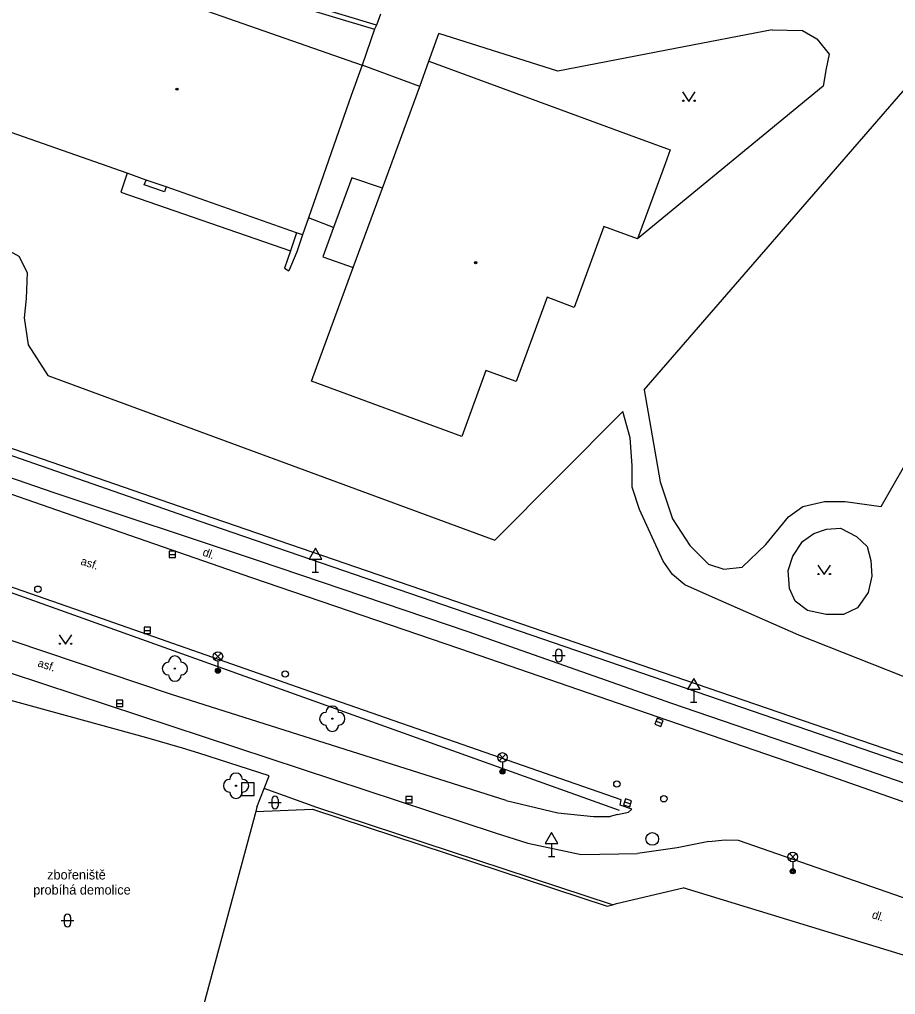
# Model space of a CAD drawing. Extents: x -598233 to -596890, y -1157848 to -1156431.
# Drawn here: x -598177.1 to -598107.9, y -1157427.1 to -1157350.2 of the extents above; entities that cross this region are included whole.
import ezdxf

# ---------------------------------------------------------------- set-up
doc = ezdxf.new("R2010")
doc.units = 0
for name, color, linetype in [('Level 10', 7, 'Continuous'), ('Level 11', 7, 'Continuous'), ('Level 22', 7, 'Continuous'), ('Level 26', 7, 'Continuous'), ('Level 27', 7, 'Continuous'), ('Level 28', 7, 'Continuous'), ('Level 33', 7, 'Continuous'), ('Level 34', 7, 'Continuous'), ('Level 36', 7, 'Continuous'), ('Level 39', 7, 'Continuous'), ('Level 40', 7, 'Continuous'), ('Level 42', 7, 'Continuous'), ('Level 5', 7, 'Continuous'), ('Level 7', 7, 'Continuous'), ('Level 9', 7, 'Continuous')]:
    doc.layers.add(name, color=color, linetype=linetype)

msp = doc.modelspace()

# ---------------------------------------------------------------- linework, layer by layer
at = {"layer": 'Level 10'}
for points in [[(-598129.85, -1157412.91), (-598128.99, -1157412.74), (-598128.74, -1157412.49), (-598129.64, -1157412.18), (-598129.56, -1157411.75), (-598154.06, -1157403.22), (-598172.16, -1157396.89), (-598187.22, -1157391.65), (-598196.64, -1157388.37), (-598205.7, -1157385.01), (-598210.18, -1157383.02), (-598212.78, -1157381.51), (-598215.97, -1157379.65), (-598220.53, -1157375.86), (-598224.65, -1157371.2), (-598227.62, -1157366.41), (-598230.19, -1157360.94), (-598232.8901, -1157353.658)], [(-598174.73, -1157388.67), (-598186.98, -1157384.41)], [(-598217.58, -1157387.43), (-598207.01, -1157391.49), (-598196.87, -1157395.42), (-598177.79, -1157401.73), (-598139.52, -1157414.37), (-598136.95, -1157415.18), (-598132.7199, -1157416.07)], [(-598158.72, -1157394.22), (-598174.73, -1157388.67)], [(-598165.15, -1157403.42), (-598194.77, -1157393.44)], [(-598142.31, -1157399.84), (-598158.72, -1157394.22)], [(-598125.89, -1157405.48), (-598142.31, -1157399.84)], [(-598138.65, -1157411.8), (-598165.15, -1157403.42)], [(-598113.03, -1157409.92), (-598125.89, -1157405.48)], [(-598099.81, -1157414.54), (-598113.03, -1157409.92)], [(-598138.65, -1157411.8), (-598134.58, -1157412.79), (-598131.75, -1157413.07), (-598130.77, -1157413.07), (-598130.43, -1157413.07)], [(-598129.85, -1157412.9099), (-598130.43, -1157413.07)], [(-598122.65, -1157415.04), (-598125.15, -1157415.53)], [(-598122.65, -1157415.04), (-598121.35, -1157414.91), (-598120.33, -1157414.94), (-598106.78, -1157419.65), (-598093.77, -1157424.14)], [(-598132.7199, -1157416.07), (-598128.27, -1157415.98)], [(-598125.15, -1157415.53), (-598128.27, -1157415.98)]]:
    msp.add_lwpolyline(points, dxfattribs=at)
at = {"layer": 'Level 11'}
for points in [[(-598173.1599, -1157343.7199), (-598172.18, -1157343.98), (-598149.05, -1157350.93)], [(-598148.88, -1157350.6), (-598173, -1157343.32)], [(-598148.56, -1157349.73), (-598148.88, -1157350.6)], [(-598148.88, -1157350.6), (-598149.05, -1157350.93)], [(-598149.05, -1157350.93), (-598150.01, -1157353.76)], [(-598144.74, -1157353.46), (-598143.95, -1157351.26)], [(-598117.66, -1157350.97), (-598125.31, -1157352.45), (-598134.56, -1157354.23), (-598143.95, -1157351.26)], [(-598117.66, -1157350.97), (-598115.26, -1157351.03), (-598114.12, -1157351.68), (-598113.15, -1157352.9), (-598113.39, -1157354.03), (-598113.63, -1157355.41), (-598128.27, -1157367.48)], [(-598127.76, -1157379.4), (-598105.11, -1157353.26), (-598103.49, -1157352.53), (-598101.95, -1157352.61), (-598100.57, -1157353.26), (-598094.72, -1157358.86), (-598072.97, -1157374.04), (-598069.72, -1157379.07), (-598068.1, -1157382.56), (-598068.18, -1157401.07)], [(-598145.47, -1157355.44), (-598150.01, -1157353.76)], [(-598168.56, -1157362.28), (-598169.07, -1157363.8), (-598155.68, -1157368.43)], [(-598165.48, -1157363.38), (-598167.07, -1157362.84)], [(-598148.42, -1157363.47), (-598150.83, -1157362.66), (-598152.27, -1157366.59), (-598154.26, -1157365.82)], [(-598152.27, -1157366.59), (-598153.11, -1157368.9), (-598150.72, -1157369.74)], [(-598154.7199, -1157367.15), (-598155.18, -1157368.49), (-598155.79, -1157370)], [(-598155.21, -1157367), (-598155.68, -1157368.43)], [(-598178.85, -1157367.89), (-598177.11, -1157368.85), (-598176.46, -1157370.14), (-598176.54, -1157372.17), (-598176.7, -1157373.72), (-598176.38, -1157375.83), (-598174.83, -1157378.26), (-598139.53, -1157391.25), (-598129.45, -1157381.1)], [(-598155.68, -1157368.43), (-598156.14, -1157369.8), (-598155.79, -1157370)], [(-598202.41, -1157378.51), (-598201.88, -1157377.34), (-598199.89, -1157378.28), (-598197.68, -1157379.21), (-598186.88, -1157383.19), (-598174.34, -1157387.5), (-598158.22, -1157392.86), (-598141.67, -1157398.47), (-598125.59, -1157404.13), (-598112.45, -1157408.63), (-598099.7, -1157413.02), (-598085.56, -1157417.95), (-598077.95, -1157420.37), (-598077.74, -1157419.93), (-598077.36, -1157419.11)], [(-598127.76, -1157379.4), (-598126.5, -1157386.66), (-598125.53, -1157389.58), (-598124.15, -1157391.69), (-598122.68, -1157393.15), (-598121.47, -1157393.56), (-598120.01, -1157393.4), (-598118.14, -1157391.61), (-598116.35, -1157389.42), (-598115.22, -1157388.61), (-598113.51, -1157388.2), (-598111.89, -1157388.2), (-598109.05, -1157388.61), (-598106.45, -1157384.06)], [(-598067.75, -1157403.84), (-598075.93, -1157407.12), (-598081.37, -1157408.25), (-598086.89, -1157408.09), (-598089.65, -1157407.68), (-598092.98, -1157407.28), (-598096.96, -1157406.3), (-598101.58, -1157404.27), (-598115.54, -1157398.76), (-598122.36, -1157395.75), (-598124.55, -1157394.78), (-598125.53, -1157393.97), (-598126.26, -1157392.91), (-598128.12, -1157388.85), (-598128.69, -1157387.07), (-598128.69, -1157385.36), (-598128.85, -1157383.17), (-598129.45, -1157381.1)], [(-598112.26, -1157390.31), (-598111, -1157390.96), (-598110.14, -1157391.77), (-598109.86, -1157392.87), (-598109.78, -1157394.09), (-598110.06, -1157395.39), (-598110.92, -1157396.6), (-598112.01, -1157397.13), (-598113.39, -1157397.13), (-598114.85, -1157396.81), (-598115.83, -1157396.08), (-598116.27, -1157395.06), (-598116.39, -1157393.64), (-598116.03, -1157392.51), (-598115.26, -1157391.37), (-598114.37, -1157390.72), (-598113.35, -1157390.4), (-598112.26, -1157390.31)], [(-598167, -1157406.85), (-598178.21, -1157403.79)], [(-598164.19, -1157407.68), (-598167, -1157406.85)], [(-598162.92, -1157408.06), (-598164.19, -1157407.68)], [(-598157.35, -1157409.87), (-598162.92, -1157408.06)], [(-598157.74, -1157410.85), (-598157.35, -1157409.87)], [(-598158.33, -1157412.34), (-598157.74, -1157410.85)], [(-598153.6, -1157412.35), (-598157.74, -1157410.85)], [(-598158.33, -1157412.34), (-598158.42, -1157412.68), (-598162.51, -1157427.88)], [(-598130.26, -1157420.05), (-598153.6, -1157412.35)]]:
    msp.add_lwpolyline(points, dxfattribs=at)
at = {"layer": 'Level 22'}
for centre in [(-598164.8, -1157401.4), (-598152.37, -1157405.35), (-598159.97, -1157410.64)]:
    msp.add_circle(centre, 0.05, dxfattribs=at)
for centre, start, end in [((-598164.8, -1157400.9), 0, 180), ((-598165.3, -1157401.4), 90, 270), ((-598164.3, -1157401.4), 270, 90), ((-598164.8, -1157401.9), 180, 0), ((-598152.37, -1157404.85), 0, 180), ((-598152.87, -1157405.35), 90, 270), ((-598151.87, -1157405.35), 270, 90), ((-598152.37, -1157405.85), 180, 0), ((-598159.97, -1157410.14), 0, 180), ((-598160.47, -1157410.64), 90, 270), ((-598159.47, -1157410.64), 270, 90), ((-598159.97, -1157411.14), 180, 0)]:
    msp.add_arc(centre, 0.5, start, end, dxfattribs=at)
at = {"layer": 'Level 26'}
msp.add_lwpolyline([(-598159.53, -1157411.41), (-598158.53, -1157411.41), (-598158.53, -1157410.41), (-598159.53, -1157410.41)], close=True, dxfattribs=at)
at = {"layer": 'Level 27'}
for p, q in [((-598165.24, -1157392.38), (-598164.74, -1157392.38)), ((-598167.23, -1157398.38), (-598166.73, -1157398.38)), ((-598169.4, -1157404.15), (-598168.9, -1157404.15)), ((-598126.8145, -1157405.5534), (-598126.3455, -1157405.7266)), ((-598146.58, -1157411.74), (-598146.08, -1157411.74)), ((-598129.2989, -1157411.9162), (-598128.8211, -1157412.0638))]:
    msp.add_line(p, q, dxfattribs=at)
for points in [[(-598165.24, -1157392.63), (-598164.74, -1157392.63), (-598164.74, -1157392.13), (-598165.24, -1157392.13)], [(-598167.23, -1157398.63), (-598166.73, -1157398.63), (-598166.73, -1157398.13), (-598167.23, -1157398.13)], [(-598169.4, -1157404.4), (-598168.9, -1157404.4), (-598168.9, -1157403.9), (-598169.4, -1157403.9)], [(-598126.9011, -1157405.7879), (-598126.4321, -1157405.9611), (-598126.2589, -1157405.4921), (-598126.7279, -1157405.3189)], [(-598146.58, -1157411.99), (-598146.08, -1157411.99), (-598146.08, -1157411.49), (-598146.58, -1157411.49)], [(-598129.3727, -1157412.1551), (-598128.8949, -1157412.3027), (-598128.7473, -1157411.8249), (-598129.2251, -1157411.6773)]]:
    msp.add_lwpolyline(points, close=True, dxfattribs=at)
msp.add_circle((-598127.11, -1157414.84), 0.5, dxfattribs=at)
at = {"layer": 'Level 28'}
for centre in [(-598175.61, -1157395.13), (-598156.09, -1157401.82), (-598129.9099, -1157410.5), (-598126.2, -1157411.67)]:
    msp.add_circle(centre, 0.25, dxfattribs=at)
at = {"layer": 'Level 33'}
for p, q in [((-598161.665, -1157400.7), (-598161.135, -1157400.17)), ((-598161.665, -1157400.17), (-598161.135, -1157400.7)), ((-598161.4, -1157400.81), (-598161.4, -1157401.56)), ((-598139.205, -1157408.67), (-598138.675, -1157408.14)), ((-598139.205, -1157408.14), (-598138.675, -1157408.67)), ((-598138.94, -1157408.78), (-598138.94, -1157409.53)), ((-598116.295, -1157416.53), (-598115.765, -1157416)), ((-598116.295, -1157416), (-598115.765, -1157416.53)), ((-598116.03, -1157416.64), (-598116.03, -1157417.39))]:
    msp.add_line(p, q, dxfattribs=at)
for centre, radius in [((-598161.4, -1157400.435), 0.375), ((-598161.4, -1157401.56), 0.2), ((-598161.4, -1157401.56), 0.1445), ((-598161.4, -1157401.56), 0.0876), ((-598138.94, -1157408.405), 0.375), ((-598138.94, -1157409.53), 0.2), ((-598138.94, -1157409.53), 0.1445), ((-598138.94, -1157409.53), 0.0876), ((-598116.03, -1157416.265), 0.375), ((-598116.03, -1157417.39), 0.2), ((-598116.03, -1157417.39), 0.1445), ((-598116.03, -1157417.39), 0.0876)]:
    msp.add_circle(centre, radius, dxfattribs=at)
at = {"layer": 'Level 34'}
for p, q in [((-598153.71, -1157392.762), (-598153.71, -1157393.78)), ((-598153.96, -1157393.78), (-598153.46, -1157393.78)), ((-598123.84, -1157403.032), (-598123.84, -1157404.05)), ((-598124.09, -1157404.05), (-598123.59, -1157404.05)), ((-598135.06, -1157415.202), (-598135.06, -1157416.22)), ((-598135.31, -1157416.22), (-598134.81, -1157416.22))]:
    msp.add_line(p, q, dxfattribs=at)
for points in [[(-598154.21, -1157392.762), (-598153.21, -1157392.762), (-598153.71, -1157391.896)], [(-598124.34, -1157403.032), (-598123.34, -1157403.032), (-598123.84, -1157402.166)], [(-598135.56, -1157415.202), (-598134.56, -1157415.202), (-598135.06, -1157414.336)]]:
    msp.add_lwpolyline(points, close=True, dxfattribs=at)
at = {"layer": 'Level 36'}
for p, q in [((-598134.996, -1157400.366), (-598133.996, -1157400.366)), ((-598134.746, -1157400.116), (-598134.746, -1157400.616)), ((-598134.246, -1157400.116), (-598134.246, -1157400.616)), ((-598157.396, -1157411.966), (-598156.396, -1157411.966)), ((-598157.146, -1157411.716), (-598157.146, -1157412.216)), ((-598156.646, -1157411.716), (-598156.646, -1157412.216)), ((-598173.776, -1157421.276), (-598172.776, -1157421.276)), ((-598173.526, -1157421.026), (-598173.526, -1157421.526)), ((-598173.026, -1157421.026), (-598173.026, -1157421.526))]:
    msp.add_line(p, q, dxfattribs=at)
for points in [[(-598124.72, -1157355.87), (-598124.22, -1157356.62), (-598123.72, -1157355.87)], [(-598114.04, -1157393.23), (-598113.54, -1157393.98), (-598113.04, -1157393.23)], [(-598173.93, -1157398.73), (-598173.43, -1157399.48), (-598172.93, -1157398.73)]]:
    msp.add_lwpolyline(points, dxfattribs=at)
for centre in [(-598124.6702, -1157356.5698), (-598123.7708, -1157356.5698), (-598113.9902, -1157393.9298), (-598113.0908, -1157393.9298), (-598173.8802, -1157399.4298), (-598172.9808, -1157399.4298)]:
    msp.add_circle(centre, 0.05, dxfattribs=at)
for centre, start, end in [((-598134.4957, -1157400.1163), 0, 180), ((-598134.4957, -1157400.6163), 180, 0), ((-598156.8957, -1157411.7163), 0, 180), ((-598156.8957, -1157412.2163), 180, 0), ((-598173.2757, -1157421.0263), 0, 180), ((-598173.2757, -1157421.5263), 180, 0)]:
    msp.add_arc(centre, 0.25, start, end, dxfattribs=at)
at = {"layer": 'Level 39'}
for centre, radius in [((-598164.64, -1157355.6599), 0.09), ((-598164.64, -1157355.6599), 0.0398), ((-598141.06, -1157369.35), 0.09), ((-598141.06, -1157369.35), 0.0398)]:
    msp.add_circle(centre, radius, dxfattribs=at)
at = {"layer": 'Level 5'}
for points in [[(-598172.78, -1157345.78), (-598150.01, -1157353.76)], [(-598154.02, -1157378.7199), (-598150.72, -1157369.74), (-598148.42, -1157363.47), (-598145.47, -1157355.44), (-598144.74, -1157353.46)], [(-598144.74, -1157353.46), (-598128.43, -1157359.45)], [(-598150.01, -1157353.76), (-598150.89, -1157356.1599)], [(-598150.89, -1157356.1599), (-598154.26, -1157365.82), (-598154.7199, -1157367.15)], [(-598168.56, -1157362.28), (-598182.86, -1157357.28)], [(-598128.43, -1157359.45), (-598125.69, -1157360.46)], [(-598125.69, -1157360.46), (-598126.09, -1157361.55)], [(-598126.09, -1157361.55), (-598128.27, -1157367.48)], [(-598167.07, -1157362.84), (-598168.56, -1157362.28)], [(-598167.2199, -1157363.2199), (-598167.07, -1157362.84)], [(-598165.61, -1157363.76), (-598167.2199, -1157363.2199)], [(-598165.48, -1157363.38), (-598165.61, -1157363.76)], [(-598155.21, -1157367), (-598165.48, -1157363.38)], [(-598130.94, -1157366.49), (-598133.29, -1157372.88)], [(-598128.27, -1157367.48), (-598130.94, -1157366.49)], [(-598154.7199, -1157367.15), (-598155.21, -1157367)], [(-598135.42, -1157372.09), (-598137.86, -1157378.74)], [(-598133.29, -1157372.88), (-598135.42, -1157372.09)], [(-598140.24, -1157377.86), (-598142.1599, -1157383.08)], [(-598137.86, -1157378.74), (-598140.24, -1157377.86)], [(-598142.1599, -1157383.08), (-598154.02, -1157378.7199)]]:
    msp.add_lwpolyline(points, dxfattribs=at)
at = {"layer": 'Level 7'}
for points in [[(-598162.99, -1157389.1), (-598203.46, -1157375.13), (-598202.32, -1157372.49)], [(-598162.81, -1157389.78), (-598203.1, -1157375.73), (-598204.12, -1157375.38)], [(-598162.63, -1157389.23), (-598162.99, -1157389.1)], [(-598077.36, -1157419.11), (-598162.81, -1157389.78)], [(-598077.19, -1157418.55), (-598124.54, -1157402.3), (-598162.63, -1157389.23)], [(-598158.42, -1157412.68), (-598153.93, -1157412.48), (-598130.67, -1157420.14), (-598130.26, -1157420.05), (-598129.94, -1157419.95), (-598124.68, -1157418.7)], [(-598098.33, -1157426.76), (-598124.68, -1157418.7)]]:
    msp.add_lwpolyline(points, dxfattribs=at)
at = {"layer": 'Level 9'}
msp.add_lwpolyline([(-598129.69, -1157412.6), (-598194.84, -1157389.28)], dxfattribs=at)

# ---------------------------------------------------------------- texts
at = {"layer": 'Level 40'}
for s, rotation, p in [('dl.', 340.384798, (-598162.66, -1157392.46)), ('asf.', 342, (-598172.29, -1157393.17)), ('asf.', 342, (-598175.68, -1157401.21)), ('dl.', 341, (-598109.83, -1157421.07))]:
    msp.add_text(s, height=0.65, rotation=rotation, dxfattribs=at).set_placement(p)
at = {"layer": 'Level 42'}
for s, p in [('zbořeniště', (-598174.88, -1157418.04)), ('probíhá demolice', (-598175.98, -1157419.23))]:
    msp.add_text(s, height=0.75, dxfattribs=at).set_placement(p)

doc.saveas('drawing.dxf')
